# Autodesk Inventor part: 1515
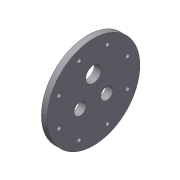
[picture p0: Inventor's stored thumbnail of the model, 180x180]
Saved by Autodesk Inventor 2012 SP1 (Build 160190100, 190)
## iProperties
Created: 2012-03
Part Number: 1515
Material: Aluminum-6061
Document SubType Name: Modeling
Designer: jdh
Density: 2.71 g/cm^3
Mass: 386.475 g
Surface Area: 362.997 cm^2
Volume: 142.611 cm^3
Author: jdh
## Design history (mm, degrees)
sketch "Sketch1"
  geometry: C1 r 76.2 at (0, 0); 1 further point
  constraints: 1 centre point, 1 coincident
  dimensions: "d0" = 152.4 diameter of C1
extrude "Extrusion1" new body sketch "Sketch1" distance "d1" = 9.525; taper "d2" = 0 deg
sketch "Sketch2"
  geometry: C1 r 76.2 at (0, 0) reference; C2 r 47.625 at (0, 0)
  constraints: 1 centre point, 1 coincident
  dimensions: "d3" = 95.25 diameter of C2
extrude "Extrusion2" join sketch "Sketch2" distance "d4" = 2.032; taper "d5" = 0 deg
sketch "Sketch3"
  geometry: L1 (-26.396, -3.683)-(-17.598, -3.683); L2 (17.598, -3.683)-(26.396, -3.683); L3 (0, 0)-(0, 25.4); L4 (0, 0)-(21.997, -12.7); L5 (0, 0)-(-21.997, -12.7); C1 r 47.625 at (0, 0) reference; C2 r 20.32 at (0, 25.4); C3 r 20.32 at (21.997, -12.7); C4 r 20.32 at (-21.997, -12.7); A1 r 10.033 centre (-21.997, -12.7) between (-26.396, -3.683) and (-17.598, -3.683); A2 r 12.763 centre (0, 25.4) between (-9.033, 34.417) and (9.033, 34.417); A3 r 10.033 centre (21.997, -12.7) between (17.598, -3.683) and (26.396, -3.683); A4 r 25.4 centre (0, 0) between (0, 25.4) and (21.997, -12.7)
  constraints: 10 end point, 9 point on circle, 7 centre point, 4 coincident, 2 equal radius, 2 horizontal, 1 perpendicular
  dimensions: "d6" = 20.066 diameter of A1; "d7" = 9.017 distance from line of L1 L5.end; "d8" = 25.527 diameter of A2; "d10" = 20.066 diameter of A3; "d11" = 9.017 distance from line of L2 L4.end; "d12" = 50.8 diameter of A4; "d13" = 120 deg angle of L4 L3; "d14" = 120 deg angle of L5 L3; "d30" = 40.64 diameter of C2
extrude "Extrusion3" cut sketch "Sketch3" stored distance "d15" = 1.524; taper "d16" = 0 deg
sketch "Sketch4" dims "d18" = 152.4 (derived), "d40" = 121.92
  geometry: L1 (0, 0)-(56.32, 23.328); L2 (0, 0)-(76.2, 0); C1 r 47.625 at (0, 0) reference; 2 further points
  constraints: 4 end point, 2 coincident, 1 horizontal, 1 horizontal alignment, 4 other
  dimensions: "d41" = 22.5 deg angle of L1 L2
hole "Hole1" sketch "Sketch4" at (56.32, 23.328) diameter "d20" = 6.7564; stored, may be unused: countersink angle "d24" = 82 deg, drill point angle "d26" = 118 deg; dims "d21" = 19.05, "d22" = 9.525, "d23" = 6.35, "d25" = 25.4
pattern_circular "Circular Pattern1" dims angle "d28" = 360 deg
sketch "Sketch6"
  geometry: L1 (-9.525, -76.2)-(-9.525, 76.2) reference; L2 (0, -76.2)-(0, 76.2) reference; L3 (2.032, 47.625)-(2.032, -47.625) reference; L4 (0, 47.625)-(0, -47.625) reference; L5 (-0.635, 54.856)-(-2.007, 54.856); L6 (-2.642, 54.221)-(-2.642, 50.868); L7 (-2.007, 50.233)-(-0.635, 50.233); L8 (4.343, 0)-(-11.836, 0) reference; L9 (-2.642, 52.544)-(0, 52.544); A1 r 0.635 centre (-0.635, 55.491) between (-0.635, 54.856) and (0, 55.491); A2 r 0.635 centre (-2.007, 54.221) between (-2.007, 54.856) and (-2.642, 54.221); A3 r 0.635 centre (-2.007, 50.868) between (-2.642, 50.868) and (-2.007, 50.233); A4 r 0.635 centre (-0.635, 49.598) between (0, 49.598) and (-0.635, 50.233); 1 further point
  constraints: 8 end point, 8 point on circle, 8 tangent, 4 centre point, 3 equal radius, 3 parallel, 3 point on line, 1 horizontal, 1 midpoint
  dimensions: "d35" = 0.635 radius of A1; "d37" = 4.6228 distance between parallel lines of L7 L5; "d42" = 2.6416 distance between parallel lines of L6 L2
revolve "Revolution1" sketch "Sketch6" stored, may be unused: angle "d39" = 90 deg
body "Solid1"
node "Projected Loop1"
node "Projected Loop2"
